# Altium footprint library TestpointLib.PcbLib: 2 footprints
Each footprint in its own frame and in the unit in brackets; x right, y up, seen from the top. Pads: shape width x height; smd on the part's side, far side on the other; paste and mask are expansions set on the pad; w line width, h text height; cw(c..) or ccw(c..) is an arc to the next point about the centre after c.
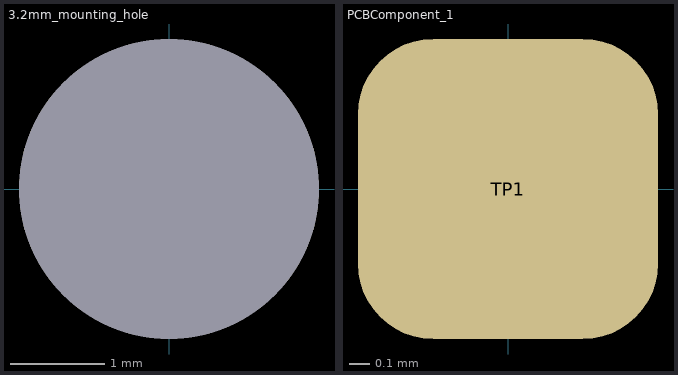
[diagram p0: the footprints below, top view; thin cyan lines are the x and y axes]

## 3.2mm_mounting_hole [mm]
pads (1):
  round 3.2 hole 3.2: ""(0,0)

## PCBComponent_1 [mm]
pads (1):
  rrect50% 1.5x1.5 smd: TP1(0,0)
